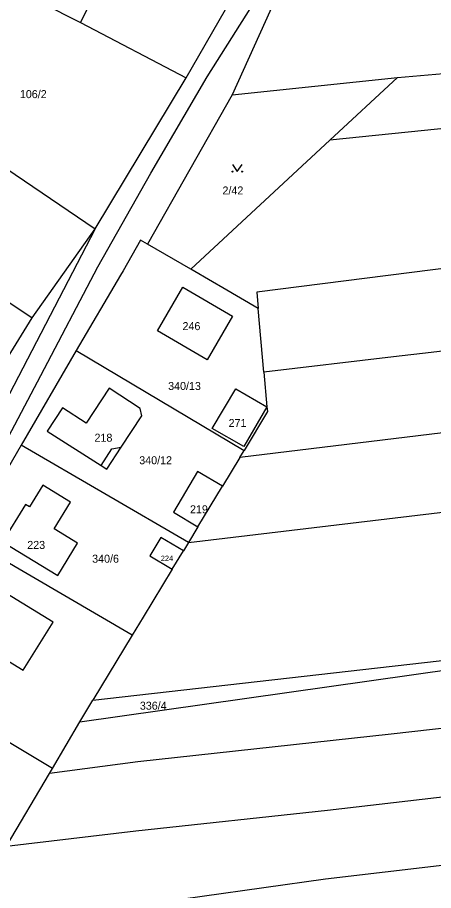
# Model space of a CAD drawing. Extents: x -747333 to -743907, y -1134120 to -1130051.
# Drawn here: x -746170.7 to -746082.4, y -1131825.9 to -1131640.4 of the extents above; entities that cross this region are included whole.
import ezdxf

# ---------------------------------------------------------------- set-up
doc = ezdxf.new("R2010")
doc.units = 0
for name, color, linetype in [('Hranice parcel', 7, 'Continuous'), ('Parcelní čísla', 7, 'Continuous'), ('Vnitřní kresba', 7, 'Continuous'), ('Značky kultur', 7, 'Continuous')]:
    doc.layers.add(name, color=color, linetype=linetype)

msp = doc.modelspace()

# ---------------------------------------------------------------- linework, layer by layer
at = {"layer": 'Hranice parcel'}
for p, q in [((-746112.88, -1131629.7), (-746125.11, -1131656.77)), ((-746134.91, -1131653.16), (-746126.56, -1131638.66)), ((-746154.22, -1131685.29), (-746134.91, -1131653.16)), ((-746125.11, -1131656.77), (-746090.01, -1131653.11)), ((-746104.37, -1131666.43), (-746090.01, -1131653.11)), ((-746125.11, -1131656.77), (-746143.09, -1131688.51)), ((-746015.44, -1131657.26), (-746104.37, -1131666.43)), ((-746133.92, -1131693.84), (-746104.37, -1131666.43)), ((-746178.01, -1131669.1), (-746154.22, -1131685.29)), ((-746167.6, -1131704.18), (-746154.22, -1131685.29)), ((-746012.9, -1131685.16), (-746119.9, -1131698.71)), ((-746191.3, -1131688.55), (-746167.6, -1131704.18)), ((-746133.92, -1131693.84), (-746143.09, -1131688.51)), ((-746119.9, -1131698.71), (-746119.59, -1131702.16)), ((-746118.38, -1131715.73), (-746119.59, -1131702.16)), ((-746173.21, -1131713.39), (-746167.6, -1131704.18)), ((-746158.27, -1131711.14), (-746169.89, -1131731.23)), ((-746158.27, -1131711.14), (-746122.58, -1131732.37)), ((-746118.38, -1131715.73), (-746117.73, -1131723.06)), ((-746009.74, -1131720.07), (-746123.47, -1131733.84)), ((-746169.89, -1131731.23), (-746181.5, -1131751.09)), ((-746134.41, -1131751.93), (-746169.89, -1131731.23)), ((-746123.47, -1131733.84), (-746122.58, -1131732.37)), ((-746123.47, -1131733.84), (-746127.17, -1131739.96)), ((-746132.45, -1131736.84), (-746137.57, -1131745.44)), ((-746134.41, -1131751.93), (-746008.22, -1131736.82)), ((-746127.17, -1131739.96), (-746132.45, -1131736.84)), ((-746132.37, -1131748.55), (-746127.17, -1131739.96)), ((-746137.57, -1131745.44), (-746132.37, -1131748.55)), ((-746132.37, -1131748.55), (-746134.41, -1131751.93)), ((-746146.31, -1131771.57), (-746181.5, -1131751.09)), ((-746140.23, -1131750.83), (-746142.61, -1131754.73)), ((-746135.47, -1131753.68), (-746140.23, -1131750.83)), ((-746134.41, -1131751.93), (-746135.47, -1131753.68)), ((-746142.61, -1131754.73), (-746137.83, -1131757.57)), ((-746137.83, -1131757.57), (-746135.47, -1131753.68)), ((-746157.45, -1131789.98), (-746005.35, -1131768.4)), ((-746154.67, -1131785.39), (-746005.35, -1131768.4)), ((-746146.31, -1131771.57), (-746154.67, -1131785.39)), ((-746163.29, -1131799.92), (-746197.7, -1131779.34)), ((-746157.45, -1131789.98), (-746154.67, -1131785.39)), ((-746163.29, -1131799.92), (-746157.45, -1131789.98)), ((-746173.02, -1131816.46), (-746163.91, -1131800.98)), ((-746163.91, -1131800.98), (-746163.29, -1131799.92))]:
    msp.add_line(p, q, dxfattribs=at)
for points in [[(-746209.77, -1131799.39), (-746188.47, -1131759.43), (-746165.71, -1131716.39), (-746153.65, -1131693.34), (-746142.41, -1131673.43), (-746130.42, -1131652.96), (-746119.1, -1131634.98), (-746122.9, -1131621.67)], [(-746178.11, -1131631.02), (-746174.04, -1131632.93), (-746157.34, -1131641.42), (-746134.91, -1131653.16)], [(-746090.01, -1131653.11), (-746078.61, -1131652.1), (-746016.41, -1131646.56)], [(-746154.22, -1131685.29), (-746175.35, -1131725.88), (-746198.19, -1131767.85), (-746214.17, -1131798.54), (-746227.58, -1131820.8), (-746249.27, -1131852.92), (-746268.11, -1131879.9), (-746296.61, -1131921.49), (-746301.25, -1131926.61)], [(-746143.09, -1131688.51), (-746144.59, -1131687.64), (-746148.26, -1131694.19), (-746148.79, -1131695.13), (-746158.27, -1131711.14)], [(-746119.59, -1131702.16), (-746127.06, -1131697.82), (-746129.27, -1131696.54), (-746133.92, -1131693.84)], [(-746125.05, -1131703.81), (-746130.42, -1131713.06), (-746140.98, -1131706.93), (-746135.62, -1131697.67), (-746125.05, -1131703.81)], [(-746011.28, -1131703.02), (-746082.88, -1131711.52), (-746090.83, -1131712.46), (-746118.38, -1131715.73)], [(-746161.12, -1131723.26), (-746164.36, -1131728.28), (-746152.94, -1131735.58), (-746151.74, -1131736.35), (-746148.66, -1131731.66), (-746144.31, -1131725.02), (-746144.66, -1131723.4), (-746151.26, -1131719.11), (-746156.08, -1131726.53), (-746161.12, -1131723.26)], [(-746117.73, -1131723.06), (-746122.65, -1131731.51), (-746129.35, -1131727.65), (-746124.3, -1131719.23), (-746117.73, -1131723.06)], [(-746117.73, -1131723.06), (-746117.64, -1131724.09), (-746122.58, -1131732.37)], [(-746162.14, -1131758.91), (-746157.95, -1131752.03), (-746162.91, -1131749), (-746159.44, -1131743.32), (-746165.34, -1131739.72), (-746168.15, -1131744.36), (-746169.01, -1131743.85), (-746173.86, -1131751.77), (-746162.14, -1131758.91)], [(-746137.83, -1131757.57), (-746144.01, -1131767.78), (-746146.31, -1131771.57)], [(-746184.77, -1131769.7), (-746169.46, -1131779.05), (-746163.11, -1131768.8), (-746178.52, -1131759.43)], [(-745872.82, -1131767.1), (-745913.22, -1131772.23), (-746038.67, -1131786.65), (-746091.32, -1131792.64), (-746145.12, -1131798.49), (-746163.91, -1131800.98)], [(-746173.02, -1131816.46), (-746145.54, -1131813.2), (-746104.87, -1131808.78), (-746061.62, -1131803.78), (-746009.82, -1131797.07), (-745872.32, -1131782.29)], [(-746182.24, -1131832.12), (-746144.56, -1131828.9), (-746105.32, -1131823.34), (-745952.05, -1131805.35), (-745871.83, -1131797.13)]]:
    msp.add_lwpolyline(points, dxfattribs=at)
at = {"layer": 'Vnitřní kresba'}
for p, q in [((-746155.06, -1131636.85), (-746157.34, -1131641.42)), ((-746152.94, -1131735.58), (-746150.67, -1131732.02)), ((-746150.67, -1131732.02), (-746148.66, -1131731.66))]:
    msp.add_line(p, q, dxfattribs=at)
at = {"layer": 'Značky kultur'}
msp.add_lwpolyline([(-746125.02, -1131671.609), (-746124.02, -1131673.11), (-746123.02, -1131671.609)], dxfattribs=at)
for centre in [(-746125.02, -1131673.109), (-746123.02, -1131673.109)]:
    msp.add_circle(centre, 0.1, dxfattribs=at)

# ---------------------------------------------------------------- texts
at = {"layer": 'Parcelní čísla'}
for s, height, p in [('106/2', 1.7, (-746170.19, -1131657.49)), ('2/42', 1.7, (-746127.17, -1131677.96)), ('246', 1.7, (-746135.654, -1131706.78)), ('340/13', 1.7, (-746138.705, -1131719.5)), ('271', 1.7, (-746125.874, -1131727.37)), ('218', 1.7, (-746154.34, -1131730.49)), ('340/12', 1.7, (-746144.84, -1131735.28)), ('219', 1.7, (-746134.06, -1131745.7)), ('223', 1.7, (-746168.62, -1131753.27)), ('340/6', 1.7, (-746154.84, -1131756.2)), ('224', 1.14, (-746140.27, -1131755.85)), ('336/4', 1.7, (-746144.71, -1131787.43))]:
    msp.add_text(s, height=height, dxfattribs=at).set_placement(p)

doc.saveas('drawing.dxf')
